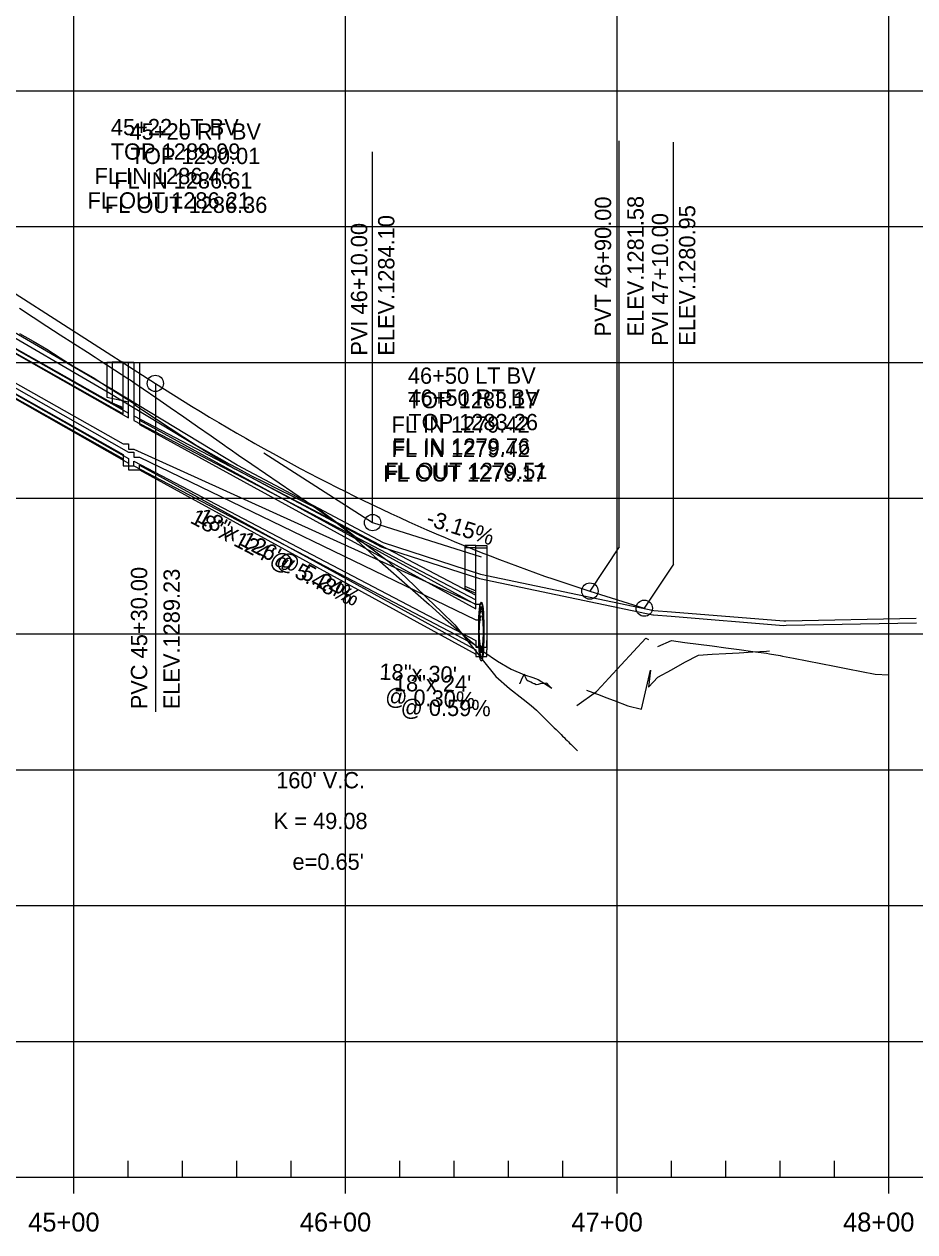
# Model space of a CAD drawing. Extents: x 670877 to 686811, y 705985 to 708501.
# Drawn here: x 685954.7 to 686282.7, y 707018.3 to 707462.9 of the extents above; entities that cross this region are included whole.
import ezdxf

# ---------------------------------------------------------------- set-up
doc = ezdxf.new("R2010")
doc.units = 0
for name, color, linetype in [('30', 7, 'Continuous'), ('37', 7, 'Continuous'), ('DRAINAGE_HGL LEFT', 7, 'Continuous'), ('DRAINAGE_HGL RIGHT', 7, 'Continuous'), ('Profile Drainage Annot Left', 7, 'Continuous'), ('Profile Drainage Annot Right', 7, 'Continuous'), ('R_Drainage Extensions_LEFT', 7, 'Continuous'), ('R_Drainage Extensions_RIGHT', 7, 'Continuous'), ('R_Drainage LEFT', 7, 'Continuous'), ('R_Drainage RIGHT', 7, 'Continuous'), ('R_Exist Surface', 7, 'Continuous'), ('R_Profile Work Left', 7, 'Continuous'), ('R_Profile Work Right', 7, 'Continuous'), ('R_Vert Alg', 7, 'Continuous'), ('R_Vert Alg Annot', 7, 'Continuous')]:
    doc.layers.add(name, color=color, linetype=linetype)

msp = doc.modelspace()

# ---------------------------------------------------------------- linework, layer by layer
at = {"layer": '37'}
for p, q in [((685973.03, 707038.43), (685973.03, 707688.43)), ((686073.03, 707038.43), (686073.03, 707688.43)), ((686173.03, 707038.43), (686173.03, 707688.43)), ((686273.03, 707038.43), (686273.03, 707688.43)), ((684473.03, 707438.43), (686573.03, 707438.43)), ((684473.03, 707388.43), (686573.03, 707388.43)), ((684473.03, 707338.43), (686573.03, 707338.43)), ((684473.03, 707288.43), (686573.03, 707288.43)), ((684473.03, 707238.43), (686573.03, 707238.43)), ((684473.03, 707188.43), (686573.03, 707188.43)), ((684473.03, 707138.43), (686573.03, 707138.43)), ((684473.03, 707088.43), (686573.03, 707088.43)), ((685993.03, 707038.43), (685993.03, 707044.43)), ((686013.03, 707038.43), (686013.03, 707044.43)), ((686033.03, 707038.43), (686033.03, 707044.43)), ((686053.03, 707038.43), (686053.03, 707044.43)), ((686093.03, 707038.43), (686093.03, 707044.43)), ((686113.03, 707038.43), (686113.03, 707044.43)), ((686133.03, 707038.43), (686133.03, 707044.43)), ((686153.03, 707038.43), (686153.03, 707044.43)), ((686193.03, 707038.43), (686193.03, 707044.43)), ((686213.03, 707038.43), (686213.03, 707044.43)), ((686233.03, 707038.43), (686233.03, 707044.43)), ((686253.03, 707038.43), (686253.03, 707044.43)), ((684473.03, 707038.43), (686573.03, 707038.43)), ((685973.03, 707032.43), (685973.03, 707038.43)), ((686073.03, 707032.43), (686073.03, 707038.43)), ((686173.03, 707032.43), (686173.03, 707038.43)), ((686273.03, 707032.43), (686273.03, 707038.43))]:
    msp.add_line(p, q, dxfattribs=at)
at = {"layer": 'DRAINAGE_HGL LEFT'}
for points in [[(685673.48, 707472.79), (685740.24, 707452.02), (685741.7, 707451.49), (685766.35, 707441.84), (685791.6, 707431.79), (685793.04, 707431.24), (685832.48, 707412.99), (685833.97, 707412.28), (685835.79, 707411.38), (685885.14, 707386.44), (685887.67, 707385.1), (685938.06, 707357.07), (685940.74, 707355.58), (685987.13, 707328.55), (686033.17, 707300.67), (686033.27, 707300.6), (686086.87, 707272.08), (686122.78, 707260.43), (686186.53, 707247.11), (686186.61, 707247.1), (686193.03, 707246.6), (686234.36, 707243.27), (686235.19, 707243.3), (686283.18, 707244.26)], [(685732.9, 707439.08), (685734.9, 707439.08), (685734.9, 707439.08), (685734.7, 707439.08), (685782.98, 707424.58), (685785.03, 707424.58), (685785.03, 707422.45), (685787.06, 707422.45), (685993.14, 707305.35), (685995.14, 707305.35), (685995.14, 707303.57), (685997.14, 707303.57), (686121.03, 707243.68), (686123.03, 707243.68)]]:
    msp.add_lwpolyline(points, dxfattribs=at)
at = {"layer": 'DRAINAGE_HGL RIGHT'}
msp.add_lwpolyline([(685732.83, 707441.79), (685734.83, 707441.79), (685734.83, 707441.79), (685734.83, 707441.79), (685783.01, 707426.79), (685785.03, 707426.79), (685785.03, 707423.69), (685787.06, 707423.69), (685991.16, 707308.49), (685993.16, 707308.49), (685993.16, 707306.41), (685995.16, 707306.41), (686121.03, 707249.44), (686123.03, 707249.44)], dxfattribs=at)
at = {"layer": 'R_Drainage Extensions_LEFT'}
for points in [[(685993.14, 707338.33), (685985.14, 707338.33), (685985.14, 707325.58), (685993.14, 707323.91), (685993.14, 707338.33)], [(686121.03, 707270.13), (686117.03, 707270.13), (686117.03, 707255.13), (686121.03, 707253.46), (686121.03, 707270.13)]]:
    msp.add_lwpolyline(points, dxfattribs=at)
at = {"layer": 'R_Drainage Extensions_RIGHT'}
for points in [[(685991.16, 707338.53), (685987.16, 707338.53), (685987.16, 707323.53), (685991.16, 707321.86), (685991.16, 707338.53)], [(686121.03, 707271.03), (686117.03, 707271.03), (686117.03, 707256.03), (686121.03, 707254.36), (686121.03, 707271.03)]]:
    msp.add_lwpolyline(points, dxfattribs=at)
at = {"layer": 'R_Drainage LEFT'}
for points in [[(685787.07, 707436.79), (685993.14, 707319.7)], [(685787.07, 707435.13), (685993.14, 707318.03)], [(685787.07, 707420.13), (685993.14, 707303.03)], [(685787.07, 707418.46), (685993.14, 707301.36)], [(685993.14, 707318.03), (685993.14, 707338.33)], [(685993.14, 707338.33), (685997.14, 707338.33)], [(685997.14, 707338.33), (685997.14, 707315.53)], [(685997.14, 707317.2), (686121.03, 707249.3)], [(685997.14, 707315.53), (686121.03, 707247.63)], [(685993.14, 707303.03), (685993.14, 707298.86)], [(685993.14, 707298.86), (685997.14, 707298.86)], [(685997.14, 707298.86), (685997.14, 707300.53)], [(685997.14, 707300.53), (686121.03, 707232.63)], [(685997.14, 707298.86), (686121.03, 707230.96)], [(686121.03, 707247.63), (686121.03, 707270.13)], [(686121.03, 707270.13), (686125.03, 707270.13)], [(686125.03, 707270.13), (686125.03, 707232.63)], [(686121.03, 707232.63), (686121.03, 707230.13)], [(686121.03, 707230.13), (686125.03, 707230.13)], [(686125.03, 707230.13), (686125.03, 707232.63)]]:
    msp.add_lwpolyline(points, dxfattribs=at)
for centre, major_axis in [((686123.03, 707240.64), (0, 7.5)), ((686123.03, 707240.13), (0, 7.5)), ((686123.03, 707237.63), (0, 9.17)), ((686123.03, 707237.63), (0, 7.5))]:
    msp.add_ellipse(centre, major_axis=major_axis, ratio=0.1, dxfattribs=at)
at = {"layer": 'R_Drainage RIGHT'}
for points in [[(685787.05, 707436.4), (685991.16, 707321.2)], [(685787.05, 707434.73), (685991.16, 707319.53)], [(685787.05, 707419.73), (685991.16, 707304.53)], [(685787.05, 707418.07), (685991.16, 707302.86)], [(685991.16, 707319.53), (685991.16, 707338.53)], [(685991.16, 707338.53), (685995.16, 707338.53)], [(685995.16, 707338.53), (685995.16, 707317.03)], [(685995.16, 707318.7), (686121.03, 707252.7)], [(685995.16, 707317.03), (686121.03, 707251.03)], [(685991.16, 707304.53), (685991.16, 707300.36)], [(685995.16, 707300.36), (685995.16, 707302.03)], [(685995.16, 707302.03), (686121.03, 707236.03)], [(685991.16, 707300.36), (685995.16, 707300.36)], [(685995.16, 707300.36), (686121.03, 707234.36)], [(686121.03, 707251.03), (686121.03, 707271.03)], [(686121.03, 707271.03), (686125.03, 707271.03)], [(686125.03, 707271.03), (686125.03, 707236.03)], [(686121.03, 707236.03), (686121.03, 707233.53)], [(686125.03, 707233.53), (686125.03, 707236.03)], [(686121.03, 707233.53), (686125.03, 707233.53)]]:
    msp.add_lwpolyline(points, dxfattribs=at)
for centre, major_axis in [((686123.03, 707241.03), (0, 9.17)), ((686123.03, 707240.64), (0, 9.17)), ((686123.03, 707241.03), (0, 7.5)), ((686123.03, 707240.64), (0, 7.5))]:
    msp.add_ellipse(centre, major_axis=major_axis, ratio=0.1, dxfattribs=at)
at = {"layer": 'R_Exist Surface'}
msp.add_lwpolyline([(685939.91, 707354.13), (685986.28, 707327.12), (686032.28, 707299.25), (686032.41, 707299.17), (686086.16, 707270.56), (686086.21, 707270.54), (686122.32, 707258.83), (686122.35, 707258.81), (686186.2, 707245.47), (686186.39, 707245.44), (686192.89, 707244.94), (686234.33, 707241.59), (686235.24, 707241.63), (686283.28, 707242.59)], dxfattribs=at)
at = {"layer": 'R_Profile Work Left'}
for points in [[(685953.03, 707349.04), (685958.03, 707346.19), (685963.03, 707343.26), (685968.03, 707340.09), (685973.03, 707336.92), (685980.09, 707332.8), (685982.98, 707330.98), (685985.2, 707329.57), (685990.32, 707326.36), (685995.64, 707323.04), (685995.84, 707322.9), (685995.86, 707322.89), (685996.09, 707322.75), (685995.46, 707322.74), (685998.46, 707320.77), (686003.46, 707317.49), (686008.46, 707314.21), (686013.47, 707310.94), (686018.47, 707307.69), (686023.47, 707304.82), (686028.47, 707302.05), (686029.15, 707301.67), (686030.24, 707301.03), (686033.24, 707299.42), (686038.24, 707296.82), (686043.24, 707294.3), (686048.23, 707291.8), (686053.23, 707289.32), (686058.23, 707286.85), (686063.23, 707284.4), (686068.24, 707280.67), (686073.24, 707276.9), (686074.86, 707275.69), (686078.25, 707273.15), (686083.25, 707269.4), (686088.26, 707265.66), (686093.27, 707261.1), (686098.28, 707256.31), (686103.29, 707251.53), (686108.3, 707246.76), (686113.32, 707241.75), (686118.34, 707235.42), (686122.37, 707230.33), (686123.36, 707229.09), (686128.37, 707222.76), (686133.39, 707218.42), (686138.39, 707214.45), (686141.4, 707212.07), (686143.4, 707210.35), (686148.42, 707205.37), (686148.65, 707205.15), (686149.28, 707204.52), (686149.92, 707203.89), (686150.55, 707203.26), (686151.17, 707202.65), (686151.78, 707202.04), (686152.38, 707201.45), (686152.96, 707200.87), (686153.43, 707200.4), (686153.53, 707200.31), (686154.07, 707199.76), (686154.59, 707199.25), (686155.09, 707198.75), (686155.56, 707198.29), (686156, 707197.85), (686156.41, 707197.45), (686156.79, 707197.07), (686157.13, 707196.74), (686157.43, 707196.43), (686157.7, 707196.17), (686157.92, 707195.94), (686158.11, 707195.76), (686158.26, 707195.61), (686158.36, 707195.51), (686158.43, 707195.45)], [(686158.22, 707212.12), (686165.41, 707217.31), (686167.23, 707219.27), (686169.97, 707222.21), (686174.53, 707227.11), (686179.1, 707232.01), (686183.66, 707236.91), (686184.64, 707236.36)], [(686188.03, 707233.88), (686193.03, 707236.01), (686198.03, 707235.34), (686203.03, 707234.68), (686208.03, 707234.01), (686213.03, 707233.35), (686218.03, 707232.68), (686223.03, 707232.02), (686228.03, 707231.31), (686229.14, 707231.12), (686233.03, 707230.45), (686233.89, 707230.3), (686238.03, 707229.57), (686243.03, 707228.57), (686248.03, 707227.57), (686253.03, 707226.57), (686258.03, 707225.57), (686263.03, 707224.57), (686268.03, 707223.62), (686273.03, 707223.39)]]:
    msp.add_lwpolyline(points, dxfattribs=at)
at = {"layer": 'R_Profile Work Right'}
for points in [[(685953.03, 707358.42), (685958.03, 707355.11), (685963.03, 707351.81), (685968.03, 707348.58), (685973.03, 707345.36), (685978.03, 707342.13), (685980.85, 707340.31), (685983.03, 707338.91), (685988.03, 707335.67), (685993.32, 707332.25), (685993.53, 707332.11), (685993.54, 707332.1), (685993.76, 707331.95), (685995.54, 707330.74), (685998.55, 707328.67), (686003.55, 707325.22), (686008.55, 707321.76), (686013.56, 707318.32), (686018.56, 707314.87), (686023.57, 707311.43), (686028.58, 707307.88), (686029.26, 707307.38), (686030.58, 707306.41), (686033.59, 707304.32), (686038.59, 707300.89), (686043.6, 707297.47), (686048.61, 707294.05), (686053.62, 707290.63), (686058.63, 707287.22), (686063.64, 707283.82), (686068.66, 707280.26), (686073.67, 707276.4), (686075.29, 707274.86), (686078.7, 707271.63), (686083.73, 707266.91), (686088.76, 707262.56), (686093.79, 707258.17), (686098.82, 707253.71), (686103.85, 707249.25), (686108.88, 707244.79), (686113.91, 707240.33), (686118.94, 707235.88), (686122.98, 707232.61), (686123.97, 707231.9), (686128.99, 707228.42), (686134, 707225.46), (686139, 707223.33), (686142, 707222.37), (686144, 707221.73), (686149.02, 707218.47), (686148.91, 707218.54), (686148.03, 707219.29), (686147.19, 707220.27), (686146.35, 707220.25), (686145.53, 707220.17), (686144.72, 707220.04), (686143.93, 707219.85), (686143.18, 707219.75), (686142.62, 707220.03), (686142.51, 707220.08), (686141.89, 707220.38), (686141.3, 707220.65), (686140.77, 707220.89), (686140.27, 707221.11), (686139.85, 707221.45), (686139.54, 707222), (686139.27, 707222.53), (686139.06, 707223.05), (686138.92, 707223.64), (686138.53, 707223.11), (686138.02, 707222.02), (686137.51, 707220.84), (686137.21, 707220.23), (686137.11, 707220.16), (686137.06, 707220.12)], [(686161.75, 707217.79), (686166.83, 707215.85), (686168.86, 707215.08), (686171.91, 707213.92), (686176.99, 707211.99), (686182, 707210.79), (686185.3, 707225.13), (686184.64, 707218.91), (686188.03, 707222.49), (686193.03, 707225.24), (686198.03, 707228), (686203.03, 707230.67), (686208.03, 707230.95), (686213.03, 707231.23), (686218.03, 707231.51), (686223.03, 707231.8), (686228.03, 707232.08), (686229.14, 707232.26)]]:
    msp.add_lwpolyline(points, dxfattribs=at)
at = {"layer": 'R_Vert Alg'}
for p, q in [((685878.03, 707410.79), (686003.03, 707330.69)), ((686043.03, 707305.06), (686083.03, 707279.43)), ((686083.03, 707279.43), (686123.03, 707266.83)), ((686173.82, 707270.46), (686163.03, 707254.23)), ((686193.82, 707264.16), (686183.03, 707247.93)), ((686163.03, 707254.23), (686183.03, 707247.93))]:
    msp.add_line(p, q, dxfattribs=at)
msp.add_lwpolyline([(686003.03, 707330.69), (686006.36, 707328.57), (686009.7, 707326.47), (686013.03, 707324.39), (686016.36, 707322.33), (686019.7, 707320.3), (686023.03, 707318.28), (686026.36, 707316.29), (686029.7, 707314.33), (686033.03, 707312.38), (686036.36, 707310.46), (686039.7, 707308.57), (686043.03, 707306.69), (686046.36, 707304.84), (686049.7, 707303.01), (686053.03, 707301.2), (686056.36, 707299.41), (686059.7, 707297.65), (686063.03, 707295.91), (686066.36, 707294.19), (686069.7, 707292.5), (686073.03, 707290.83), (686076.36, 707289.18), (686079.7, 707287.55), (686086.36, 707284.36), (686089.7, 707282.8), (686093.03, 707281.27), (686096.36, 707279.75), (686099.7, 707278.26), (686103.03, 707276.79), (686106.36, 707275.35), (686109.7, 707273.93), (686113.03, 707272.52), (686116.36, 707271.15), (686119.7, 707269.79), (686123.03, 707268.46), (686126.36, 707267.15), (686129.7, 707265.86), (686133.03, 707264.6), (686136.36, 707263.35), (686139.7, 707262.13), (686143.03, 707260.94), (686146.36, 707259.76), (686149.7, 707258.61), (686153.03, 707257.48), (686156.36, 707256.37), (686159.7, 707255.29), (686163.03, 707254.23)], dxfattribs=at)
for centre in [(686003.03, 707330.69), (686083.03, 707279.43), (686163.03, 707254.23), (686183.03, 707247.93)]:
    msp.add_circle(centre, 3, dxfattribs=at)
at = {"layer": 'R_Vert Alg Annot'}
for p, q in [((686173.82, 707270.46), (686173.82, 707420.04)), ((686193.82, 707264.16), (686193.82, 707419.54)), ((686083.03, 707279.43), (686083.03, 707415.9)), ((686003.03, 707330.69), (686003.03, 707209.71))]:
    msp.add_line(p, q, dxfattribs=at)

# ---------------------------------------------------------------- texts
at = {"layer": '30'}
for s, p in [('45+00', (685956.22, 707018.43)), ('46+00', (686056.22, 707018.43)), ('47+00', (686156.22, 707018.43)), ('48+00', (686256.22, 707018.43))]:
    msp.add_text(s, height=7, dxfattribs=at).set_placement(p)
at = {"layer": 'Profile Drainage Annot Left'}
for s, p in [('45+22 LT BV', (685986.68, 707422.04)), ('TOP 1289.99', (685986.62, 707413.04)), ('FL IN 1286.46', (685980.65, 707404.04)), ('FL OUT 1286.21', (685978.09, 707395.04)), ('46+50 LT BV', (686096.01, 707330.54)), ('TOP 1283.17', (686095.97, 707321.54)), ('FL IN 1279.42', (686089.98, 707312.54)), ('FL IN 1279.42', (686089.98, 707303.54)), ('FL OUT 1279.17', (686086.97, 707294.54))]:
    msp.add_text(s, height=6, dxfattribs=at).set_placement(p)
for s, rotation, p in [('18"x 124\'@ 5.48%', 332.447, (686015.46, 707279.54)), ('18"x 24\'', 359.6154, (686090.85, 707217.36)), ('@ 0.59%', 359.6154, (686093.34, 707208.35))]:
    msp.add_text(s, height=6, rotation=rotation, dxfattribs=at).set_placement(p)
at = {"layer": 'Profile Drainage Annot Right'}
for s, p in [('45+20 RT BV', (685993.53, 707420.43)), ('TOP 1290.01', (685993.94, 707411.43)), ('FL IN 1286.61', (685987.94, 707402.43)), ('FL OUT 1286.36', (685984.5, 707393.43)), ('46+50 RT BV', (686096.21, 707322.44)), ('TOP 1283.26', (686096.18, 707313.44)), ('FL IN 1279.76', (686090.18, 707304.44)), ('FL OUT 1279.51', (686087.62, 707295.44))]:
    msp.add_text(s, height=6, dxfattribs=at).set_placement(p)
for s, rotation, p in [('18"x 126\'@ 5.24%', 331.5729, (686018.11, 707279.88)), ('18"x 30\'', 357.4483, (686085.42, 707221.63)), ('@ 0.30%', 357.4483, (686087.56, 707212.53))]:
    msp.add_text(s, height=6, rotation=rotation, dxfattribs=at).set_placement(p)
at = {"layer": 'R_Vert Alg Annot'}
for s, rotation, p in [('PVT 46+90.00', 90, (686170.82, 707347.96)), ('ELEV.1281.58', 90, (686182.82, 707347.96)), ('ELEV.1280.95', 90, (686201.82, 707344.54)), ('ELEV.1284.10', 90, (686091.03, 707340.9)), ('PVI 47+10.00', 90, (686191.82, 707344.54)), ('PVI 46+10.00', 90, (686081.03, 707340.9)), ('-3.15%', 342.5156, (686102.39, 707278.6)), ('PVC 45+30.00', 90, (686000.03, 707210.71)), ('ELEV.1289.23', 90, (686012.03, 707210.71))]:
    msp.add_text(s, height=6, rotation=rotation, dxfattribs=at).set_placement(p)
for s, p in [("160' V.C.", (686047.52, 707181.61)), ('K = 49.08', (686046.59, 707166.61)), ("e=0.65'", (686053.52, 707151.61))]:
    msp.add_text(s, height=6, dxfattribs=at).set_placement(p)

doc.saveas('drawing.dxf')
